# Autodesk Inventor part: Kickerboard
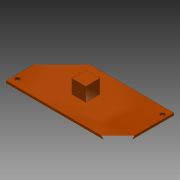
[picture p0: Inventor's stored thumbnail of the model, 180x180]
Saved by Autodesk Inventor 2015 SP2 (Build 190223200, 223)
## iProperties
Created: 2012-08
Part Number: Kickerboard
Material: Phenolharz
Document SubType Name: Modeling
Designer: rYan
Mass: 8.37457 g
Surface Area: 71.84 cm^2
Volume: 6.06853 cm^3
Density: 1.38 g/cm^3
Appearance: Glatt - hellorange
Author: rYan
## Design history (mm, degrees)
sketch "Skizze1"
  geometry: L1 (-40, 20)-(40, 20); L2 (40, 20)-(40, -20); L3 (40, -20)-(-40, -20); L4 (-40, -20)-(-40, 20); L5 (0, 28)-(0, -28) reference; L6 (-56, 0)-(56, 0) reference; 1 further point
  constraints: 8 end point, 2 parallel, 1 horizontal, 1 perpendicular, 2 other
  dimensions: "d0" = 80 distance of L1.start L1.end; "d1" = 40 distance of L3.end L1.start
extrude "Extrusion1" new body sketch "Skizze1" distance "d2" = 1.6; taper "d3" = 0 deg
sketch "Skizze2"
  geometry: L1 (-8, 5)-(2, 5); L2 (2, 5)-(2, -5); L3 (2, -5)-(-8, -5); L4 (-8, -5)-(-8, 5); L5 (-56, 0)-(56, 0) reference; L6 (40, -20)-(40, 20) reference; 1 further point
  constraints: 8 end point, 2 parallel, 1 horizontal, 1 perpendicular, 1 other
  dimensions: "d4" = 10 distance of L3.end L1.start; "d6" = 10 distance of L1.start L1.end; "d7" = 38 distance between parallel lines of L6 L2
extrude "Extrusion2" join sketch "Skizze2" distance "d8" = 10; taper "d9" = 0 deg
sketch "Skizze3"
  geometry: L1 (40, 20)-(-40, 20) reference; L2 (-40, -20)-(-40, 20) reference; 2 further points
  dimensions: "d10" = 5 distance from line of L1 point (-37, 15); "d11" = 3 distance from line of L2 point (-37, 15)
hole "Bohrung1" sketch "Skizze3" at (-37, 15) diameter "d12" = 3.2; stored, may be unused: countersink angle "d16" = 90 deg, drill point angle "d18" = 118 deg; dims "d13" = 6, "d14" = 4, "d15" = 2, "d17" = 8
pattern_linear "Rechteckige Anordnung1" dims "d21" = 74
node "Volumenkörper1"
